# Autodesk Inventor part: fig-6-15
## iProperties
Created: 2004-05
Part Number: fig-6-15
Document SubType Name: Modeling
Designer: CADCIM Technologies
Manufacturer: Standard
Standards Organization: Custom
Author: CADCIM Technologies
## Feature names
1. Extrusion1
2. Extrusion2
3. Extrusion3
